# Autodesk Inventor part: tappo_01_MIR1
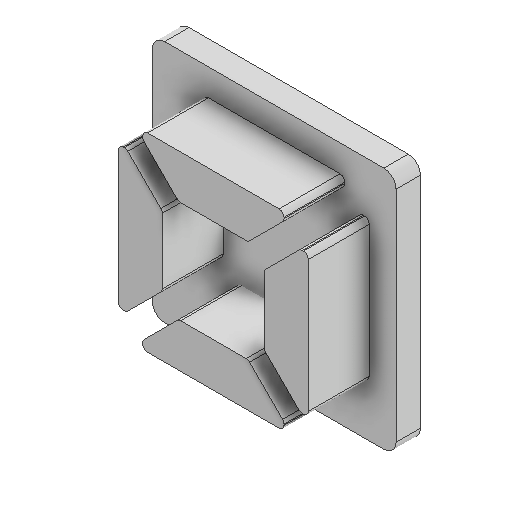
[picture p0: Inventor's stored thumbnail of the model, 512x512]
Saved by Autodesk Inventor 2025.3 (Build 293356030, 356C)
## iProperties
Created: 2026-02
Part Number: tappo_01_MIR1
Material: Generico
Document SubType Name: Modeling
Designer: R5800u
Density: 1 g/cm^3
Appearance: Default
Author: R5800u
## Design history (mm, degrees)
derived "tappo_01.ipt"
  sketch "Schizzo1"
    geometry: L1 (-10, 10)-(10, 10) reference; L2 (10, 10)-(10, -10) reference; L3 (10, -10)-(-10, -10) reference; L4 (-10, -10)-(-10, 10) reference; L5 (-10, 10)-(10, -10) reference; L6 (10, 10)-(-10, -10) reference; L7 (-6, -8)-(-3, -8) reference; L8 (-6, -7.061)-(-6, -8) reference; L9 (-2.939, -4)-(-6, -7.061) reference; L10 (0, 0)-(0, -10) reference; L11 (-2.939, -4)-(0, -4) reference; L12 (-3, -8)-(0, -8) reference; L13 (0, -7.8)-(-3, -7.8) reference; L14 (-3, -7.8)-(-5.8, -7.8) reference; L15 (-5.8, -7.8)-(-5.8, -7.144) reference; L16 (-5.8, -7.144)-(-2.856, -4.2) reference; L17 (-2.856, -4.2)-(0, -4.2) reference; L18 (0, -7.8)-(3, -7.8) reference; L19 (3, -7.8)-(5.8, -7.8) reference; L20 (5.8, -7.8)-(5.8, -7.144) reference; L21 (5.8, -7.144)-(2.856, -4.2) reference; L22 (2.856, -4.2)-(0, -4.2) reference
feature "Solido1::tappo_01.ipt"
feature "Solido2::tappo_01.ipt"
tag "Lavorazione contrassegno1"
node "Solido1"
node "Solido2"
